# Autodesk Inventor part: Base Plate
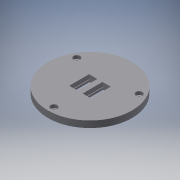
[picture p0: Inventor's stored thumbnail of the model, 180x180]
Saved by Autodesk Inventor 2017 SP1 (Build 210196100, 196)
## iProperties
Created: 2016-12
Part Number: Base Plate
Material: Generic
Document SubType Name: Modeling
Designer: HP_ELITE
Density: 1 g/cm^3
Appearance: Default
Author: HP_ELITE
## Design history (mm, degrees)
sketch "Sketch1"
  geometry: C1 r 38.5 at (0, 0); 1 further point
  constraints: 1 centre point, 1 coincident
  dimensions: "d0" = 77 diameter of C1
extrude "Extrusion1" new body sketch "Sketch1" distance "d1" = 6; taper "d2" = 0 deg
sketch "Sketch2"
  geometry: C1 r 1.75 at (0, -33); C2 r 1.75 at (28.579, 16.5); C3 r 1.75 at (-28.579, 16.5); C4 r 38.5 at (0, 0) reference; 2 further points
  constraints: 3 centre point, 2 vertical alignment, 1 coincident, 9 other
  dimensions: "d3" = 3.5 diameter of C1; "d6" = 360 deg dimension on point (0, 0) C1.centre (derived); "d8" = 5.5 dimension on C4
extrude "Extrusion2" cut sketch "Sketch2" stored distance "d9" = 6; taper "d10" = 0 deg
sketch "Sketch3"
  geometry: C1 r 1.75 at (0, -33) reference; C2 r 1.75 at (28.579, 16.5) reference; C3 r 1.75 at (-28.579, 16.5) reference; C4 r 3 at (0, -33); C5 r 3 at (-28.579, 16.5); C6 r 3 at (28.579, 16.5); 1 further point
  constraints: 3 centre point, 3 coincident, 2 equal radius
  dimensions: "d11" = 6 diameter of C4
extrude "Extrusion3" cut sketch "Sketch3" distance "d12" = 3; taper "d13" = 0 deg
sketch "Sketch4"
  geometry: L1 (-38.5, 0)-(38.5, 0) reference; L2 (-9.4, 0)-(-9.4, 1.95); L3 (-9.4, 1.95)-(-9.9, 1.95); L4 (-9.9, 1.95)-(-9.9, 6); L5 (-9.9, 6)-(-2.4, 6); L6 (38.5, 6)-(-38.5, 6) reference; L7 (-2.4, 1.95)-(-2.9, 1.95); L8 (-2.9, 1.95)-(-2.9, 0); L9 (-2.9, 0)-(-9.4, 0); L10 (-2.4, 1.95)-(-2.4, 6); L11 (0, 0)-(0, 8.177); L12 (9.4, 0)-(9.4, 1.95); L13 (9.4, 1.95)-(9.9, 1.95); L14 (9.9, 1.95)-(9.9, 6); L15 (9.9, 6)-(2.4, 6); L16 (2.4, 1.95)-(2.9, 1.95); L17 (2.9, 1.95)-(2.9, 0); L18 (2.9, 0)-(9.4, 0); L19 (2.4, 1.95)-(2.4, 6)
  constraints: 34 end point, 8 symmetric about line, 6 point on line, 4 perpendicular, 3 vertical, 1 collinear, 1 horizontal
  dimensions: "d14" = 6.5 distance between parallel lines of L2 L8; "d15" = 2.4 distance from line of L11.start L10; "d16" = 7.5 distance of L4.end L5.end; "d17" = 1.95 distance of L7.end L8.end
extrude "Extrusion4" cut sketch "Sketch4" stored distance "d18" = 18.25; taper "d19" = 0 deg
sketch "Sketch6"
  geometry: C1 r 1.075 at (0, 2.5) reference; C2 r 1.075 at (0, -2.5) reference; C3 r 1.5 at (0, 2.5); C4 r 1.5 at (0, -2.5); 1 further point
  constraints: 2 centre point, 2 coincident, 1 equal radius
  dimensions: "d22" = 3 diameter of C4
extrude "Extrusion6" cut sketch "Sketch6" distance "d23" = 4; taper "d24" = 0 deg
chamfer "Chamfer1" distance "d25" = 1.5; stored, may be unused: second distance "d26" = 2, angle "d27" = 45 deg
sketch "Sketch7"
  geometry: L1 (2.25, 16.801)-(-2.25, 16.801); L2 (-2.25, 16.801)-(-2.25, 41.801); L3 (-2.25, 41.801)-(2.25, 41.801); L4 (2.25, 41.801)-(2.25, 16.801); L5 (-2.25, 41.801)-(2.25, 16.801); 2 further points
  constraints: 10 end point, 2 parallel, 1 horizontal, 1 midpoint, 1 perpendicular, 1 vertical alignment
  dimensions: "d28" = 4.5 distance of L1.start L1.end; "d29" = 25 distance of L1.end L2.end
extrude "Extrusion7" cut sketch "Sketch7" distance "d30" = 3; taper "d31" = 0 deg
chamfer "Chamfer2" distance "d32" = 2.25; stored, may be unused: second distance "d33" = 2, angle "d34" = 45 deg
sketch "Sketch5"
  geometry: C1 r 17.777 at (0, 0); C2 r 55.213 at (0, 0); 1 further point
  constraints: 2 centre point, 2 coincident
extrude "Extrusion5" cut sketch "Sketch5" distance "d20" = 18.25; taper "d21" = 0 deg
body "Solid1"
node "Reference1"
node "Reference2"
